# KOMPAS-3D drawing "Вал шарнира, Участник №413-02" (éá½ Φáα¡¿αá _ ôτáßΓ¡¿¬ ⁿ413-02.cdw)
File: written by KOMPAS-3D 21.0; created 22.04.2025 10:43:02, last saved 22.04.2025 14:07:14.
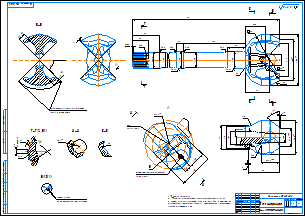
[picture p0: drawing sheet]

Sheet 1: A1, landscape

Document properties: Автор: adm; Знак неуказанной шероховатости: 4; Параметр неуказанной шероховатости: Ra 6,3; Полное имя файла: Вал шарнира _ Участник №413-02.m3d; Масса: 9.1

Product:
- Part/product: Вал шарнира  | designation Участник №413-02
    Материал: Сталь 27ХГР ГОСТ 4543-2016 (density 7850 kg/m3)
    Масса: 9.111738
    Форматы листов документа: A1

Title block, sheet 1: Наименование: Вал шарнира; designation: Участник №413-02; Материал: Сталь 27ХГР ГОСТ 4543-2016; Масса: 9,1; Количество листов документа: 1; Форматы листов документа: A1; stored path: D:\OLIMPGM-2025№1\Г-413\№2\Вал шарнира.cdw

Views: Проекционный вид 3, Местный разрез 1, Разрез В-В, Разрез Е-Е, Разрез 8, Выносной элемент 9, Вид по стрелке А, Разрез Д-Д, Разрез Г-Г, Выносной элемент Б, Выносной элемент
Referenced files in D:\OLIMPGM-2025№1\Г-413\№2\: Вал шарнира.m3d, Вал шарнира _ Участник №413-02.m3d
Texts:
  Слой 1
  Линейный размер
  Радиальный размер
  Плоскости проходящие через центры
  ручьев и центр сферы
  Острые кромки
  см. п.3 технических требований
  Ra 6,3
  Ra 6,3 ( )
  Стили документа
  Участник №413-02 Вал шарнира
Dimensions and other numbers on the sheet: 5; 36; 68; 84; 14; 25; 2; 50,38; 50,67; 62; 92,5; 20; 41,8; 39,2; 4,1; 16 шлицев; 0,5; 1:1; 1; 9,1

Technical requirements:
  *Размеры для справок.
  **Размеры обеспечиваются при выполнении размеров по п.1.
  Острые кромки обеспечить радиусом ручья R20 и сферой  35.
  Максимальные отклонения размеров от номинальных значений не
  должны превышать 0,1 мм.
